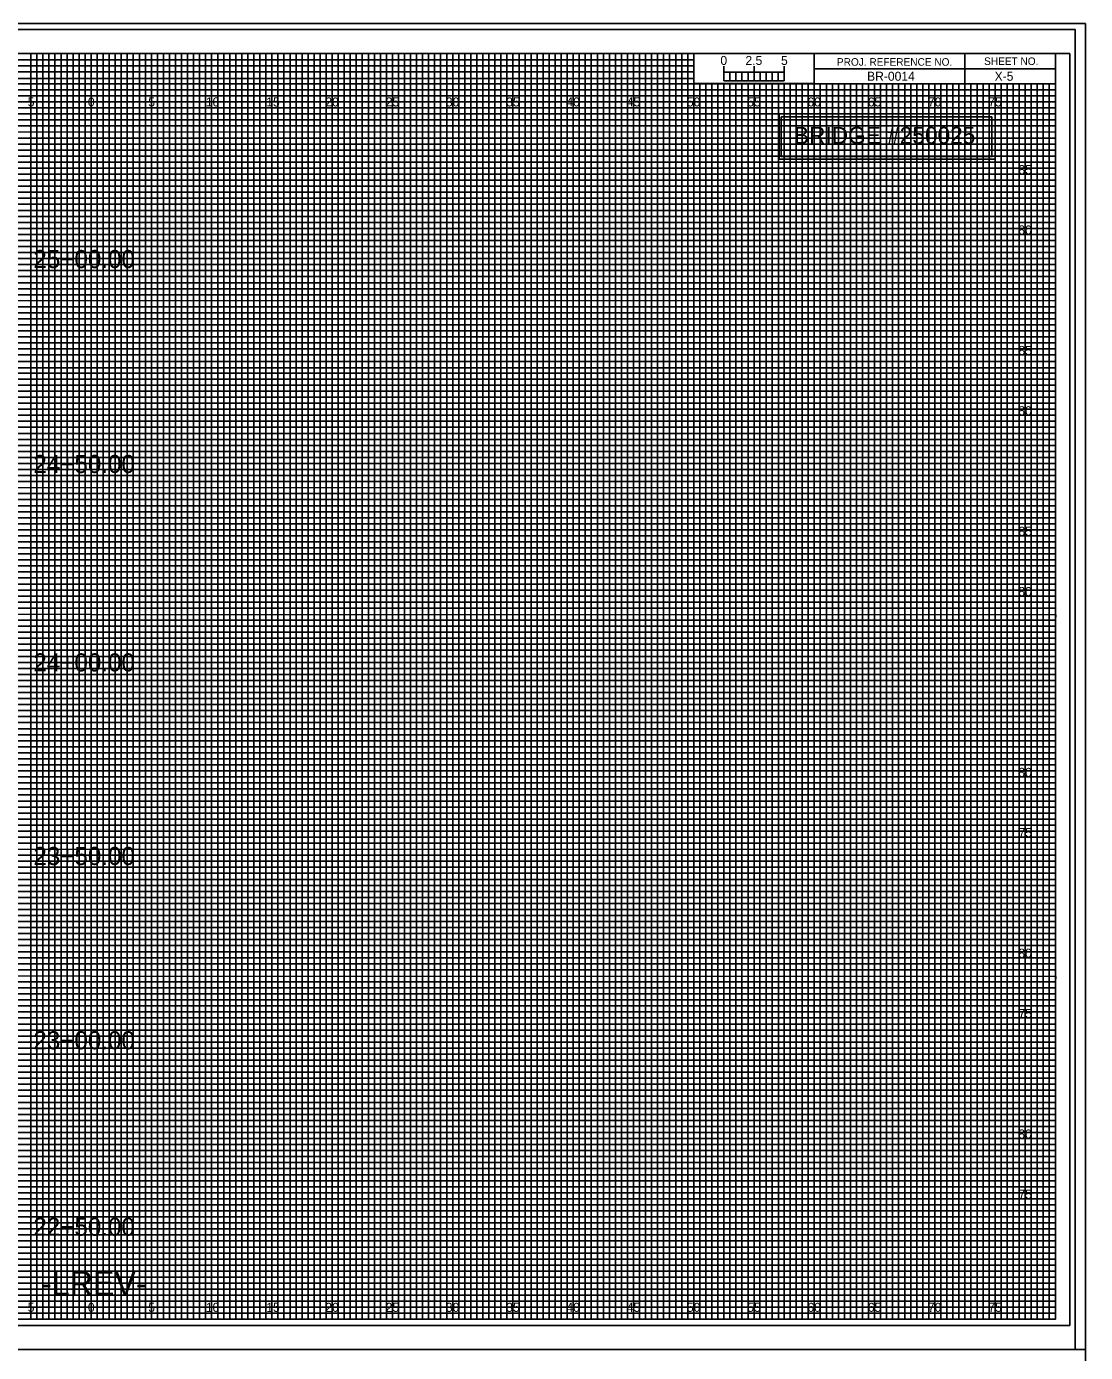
# Model space of a CAD drawing. Extents: x -8 to 533, y -20 to 768.
# Drawn here: x 74.6 to 162.5, y 437.2 to 547.2 of the extents above; entities that cross this region are included whole.
import ezdxf

# ---------------------------------------------------------------- set-up
doc = ezdxf.new("R2010")
doc.units = 0
for name, color, linetype in [('Old_Level_1', 7, 'Continuous'), ('Old_Level_34', 7, 'Continuous'), ('Prop Grid Mask', 7, 'Continuous'), ('Prop XS Alignment Label', 7, 'Continuous'), ('Prop XS Bar Scale Labels', 7, 'Continuous'), ('Prop XS Elevation Labels', 7, 'Continuous'), ('Prop XS Offset Labels', 7, 'Continuous'), ('Prop XS Project Number', 7, 'Continuous'), ('Prop XS Sheet Number', 7, 'Continuous'), ('Prop XS Station Labels', 7, 'Continuous'), ('Sheet Cross Section CELL', 7, 'Continuous'), ('Sheet Cross Section Grid Major CELL', 7, 'Continuous'), ('Sheet Cross Section Grid Middle CELL', 7, 'Continuous'), ('Sheet Cross Section Grid Minor 1 CELL', 7, 'Continuous'), ('Sheet Cross Section Grid Minor 2 CELL', 7, 'Continuous'), ('Sheet Cross Section Scale CELL', 7, 'Continuous'), ('Sheet Cutting Line CELL', 7, 'Continuous'), ('Sheet DOT Grid CELL', 7, 'Continuous'), ('Sheet Plot Border Inside CELL', 7, 'Continuous'), ('Sheet Plot Border Outside CELL', 7, 'Continuous'), ('WEI Plot Border', 7, 'Continuous')]:
    doc.layers.add(name, color=color, linetype=linetype)

msp = doc.modelspace()

# ---------------------------------------------------------------- linework, layer by layer
at = {"layer": 'Old_Level_34'}
msp.add_lwpolyline([(137.26, 539.75), (154.74, 539.75), (154.74, 536.46), (137.26, 536.46)], close=True, dxfattribs=at)
at = {"layer": 'Prop Grid Mask'}
msp.add_lwpolyline([(137.08, 540), (155, 540), (155, 536.24), (137.08, 536.24)], close=True, dxfattribs=at)
at = {"layer": 'Sheet Cross Section CELL'}
for p, q in [((152.5, 545), (152.5, 542.5)), ((152.5, 542.5), (152.5, 545)), ((160, 543.75), (140, 543.75)), ((140, 543.75), (140, 542.5)), ((140, 542.5), (160, 542.5))]:
    msp.add_line(p, q, dxfattribs=at)
for points in [[(160, 545), (0, 545), (0, 440), (160, 440)], [(140, 545), (130, 545), (130, 542.51), (140, 542.51)], [(160, 545), (140, 545), (140, 542.5), (160, 542.5)]]:
    msp.add_lwpolyline(points, close=True, dxfattribs=at)
at = {"layer": 'Sheet Cross Section Grid Major CELL'}
for p, q in [((75, 545), (70, 545)), ((75, 440), (75, 545)), ((85, 545), (80, 545)), ((80, 545), (80, 440)), ((85, 440), (85, 545)), ((95, 545), (90, 545)), ((90, 545), (90, 440)), ((95, 440), (95, 545)), ((105, 545), (100, 545)), ((100, 545), (100, 440)), ((105, 440), (105, 545)), ((115, 545), (110, 545)), ((110, 545), (110, 440)), ((115, 440), (115, 545)), ((125, 545), (120, 545)), ((120, 545), (120, 440)), ((125, 440), (125, 545)), ((130, 545), (130, 440)), ((135, 440), (135, 542.5)), ((145, 542.5), (140, 542.5)), ((140, 542.5), (140, 440)), ((145, 440), (145, 542.5)), ((155, 542.5), (150, 542.5)), ((150, 542.5), (150, 440)), ((155, 440), (155, 542.5)), ((80, 440), (75, 440)), ((90, 440), (85, 440)), ((100, 440), (95, 440)), ((110, 440), (105, 440)), ((120, 440), (115, 440)), ((130, 440), (125, 440)), ((140, 440), (135, 440)), ((150, 440), (145, 440)), ((160, 440), (155, 440)), ((160, 440), (160, 440))]:
    msp.add_line(p, q, dxfattribs=at)
for points in [[(0, 540), (160, 540), (160, 535), (0, 535)], [(0, 530), (160, 530), (160, 525), (0, 525)], [(0, 520), (160, 520), (160, 515), (0, 515)], [(0, 510), (160, 510), (160, 505), (0, 505)], [(0, 500), (160, 500), (160, 495), (0, 495)], [(0, 490), (160, 490), (160, 485), (0, 485)], [(0, 480), (160, 480), (160, 475), (0, 475)], [(0, 470), (160, 470), (160, 465), (0, 465)], [(0, 460), (160, 460), (160, 455), (0, 455)], [(0, 450), (160, 450), (160, 445), (0, 445)]]:
    msp.add_lwpolyline(points, dxfattribs=at)
at = {"layer": 'Sheet Cross Section Grid Middle CELL'}
for points in [[(72.5, 440), (77.5, 440), (77.5, 545), (82.5, 545), (82.5, 440), (87.5, 440), (87.5, 545), (92.5, 545), (92.5, 440), (97.5, 440), (97.5, 545), (102.5, 545), (102.5, 440), (107.5, 440), (107.5, 545), (112.5, 545), (112.5, 440), (117.5, 440), (117.5, 545), (122.5, 545), (122.5, 440), (127.5, 440), (127.5, 545), (129.97, 545), (130, 545), (130, 542.5), (132.5, 542.5), (132.5, 440), (137.5, 440), (137.5, 542.5), (142.5, 542.5), (142.5, 440), (147.5, 440), (147.5, 542.5), (152.5, 542.5), (152.5, 440), (157.5, 440), (157.5, 542.5)], [(0, 542.5), (137.5, 542.5)], [(0, 532.5), (160, 532.5), (160, 537.5), (0, 537.5)], [(0, 522.5), (160, 522.5), (160, 527.5), (0, 527.5)], [(0, 512.5), (160, 512.5), (160, 517.5), (0, 517.5)], [(0, 502.5), (160, 502.5), (160, 507.5), (0, 507.5)], [(0, 492.5), (160, 492.5), (160, 497.5), (0, 497.5)], [(0, 482.5), (160, 482.5), (160, 487.5), (0, 487.5)], [(0, 472.5), (160, 472.5), (160, 477.5), (0, 477.5)], [(0, 462.5), (160, 462.5), (160, 467.5), (0, 467.5)], [(0, 452.5), (160, 452.5), (160, 457.5), (0, 457.5)], [(0, 442.5), (160, 442.5), (160, 447.5), (0, 447.5)]]:
    msp.add_lwpolyline(points, dxfattribs=at)
at = {"layer": 'Sheet Cross Section Grid Minor 1 CELL'}
for p, q in [((0, 544.5), (130, 544.5)), ((130, 543.99), (0, 543.99)), ((0, 543.5), (130, 543.5)), ((130, 544.5), (130, 543.99)), ((130, 543.5), (130, 542.95)), ((130, 542.95), (0, 542.95)), ((0, 542), (160, 542))]:
    msp.add_line(p, q, dxfattribs=at)
for points in [[(0, 541.5), (135, 541.5), (160, 541.5), (160, 541), (0, 541)], [(0, 540.5), (160, 540.5), (160, 539.5), (0, 539.5)], [(0, 539), (160, 539), (160, 538.5), (0, 538.49)], [(0, 538), (160, 538), (160, 537), (0, 537)], [(0, 536.5), (160, 536.5), (160, 536), (0, 536)], [(0, 535.5), (160, 535.5), (160, 534.5), (0, 534.5)], [(0, 534), (160, 534), (160, 533.5), (0, 533.5)], [(0, 533), (160, 533), (160, 532), (0, 532)], [(0, 531.5), (160, 531.5), (160, 531), (0, 531)], [(0, 530.5), (160, 530.5), (160, 529.5), (0, 529.5)], [(0, 529), (160, 529), (160, 528.5), (0, 528.5)], [(0, 528), (160, 528), (160, 526.98), (160, 526.5), (160, 526), (0, 526)], [(0, 527), (160, 527), (160, 526.5), (0, 526.5)], [(0, 525.5), (160, 525.5), (160, 524.5), (0, 524.51)], [(0, 524.51), (160, 524.5), (160, 524), (0, 524)], [(0, 523.5), (160, 523.5), (160, 523), (0, 523)], [(0, 522), (160, 522), (160, 521.5), (0, 521.5)], [(0, 521), (160, 521), (160, 520.5), (0, 520.5)], [(-0.04, 519.45), (160, 519.45), (160, 518.94), (-0.04, 518.94)], [(0, 518.5), (160, 518.5), (160, 518), (0, 518)], [(0, 517), (160, 517), (160, 516.5), (0, 516.5)], [(0, 516), (160, 516), (160, 515.5), (0, 515.5)], [(0, 514.5), (160, 514.5), (160, 514), (0, 514)], [(0, 513.5), (160, 513.5), (160, 513), (0, 513)], [(0, 512), (160, 512), (160, 511.5), (0, 511.5)], [(0, 511), (160, 511), (160, 510.5), (0, 510.5)], [(0, 509.5), (160, 509.5), (160, 508.99), (0, 509)], [(0, 508.5), (160, 508.5), (160, 508), (0, 508)], [(0, 507), (160, 507), (160, 506.5), (0, 506.5)], [(0, 506), (160, 506), (160, 505.5), (0, 505.5)], [(0, 504.5), (160, 504.5), (160, 504), (0, 504)], [(0, 503.5), (160, 503.5), (160, 503), (0, 503)], [(0, 502), (160, 502), (160, 501.5), (0, 501.5)], [(0, 501), (160, 501), (160, 500.5), (0, 500.5)], [(0, 499.5), (160, 499.5), (160, 499), (0, 499)], [(0, 498.5), (160.03, 498.45), (160, 498), (0, 498)], [(0, 497), (160, 497), (160, 496.5), (0, 496.5)], [(0, 496), (160, 496), (160, 495.5), (0, 495.5)], [(0, 494.5), (160, 494.5), (160, 494), (0, 494)], [(0, 493.5), (160, 493.5), (160, 493), (0, 493)], [(0, 492), (160, 492), (160, 491.5), (0, 491.5)], [(0, 491), (160, 491), (160, 490.5), (0, 490.5)], [(0, 489.5), (160, 489.5), (160, 489), (0, 489)], [(0, 488.5), (160, 488.5), (160, 488), (0, 488)], [(0, 487), (160, 487), (160, 486.5), (0, 486.5)], [(0, 486), (160, 486), (160, 485.5), (0, 485.5)], [(0, 484.5), (160, 484.5), (160, 484), (0, 484)], [(0, 483.5), (160, 483.5), (160, 483), (0, 483)], [(0, 482), (160, 482), (160, 481.5), (0, 481.5)], [(0, 481), (160, 481), (160, 480.5), (0, 480.5)], [(0, 479.5), (160, 479.5), (160, 478.99), (0, 479)], [(0, 478.5), (160, 478.5), (160, 478), (0, 478)], [(0, 477), (160, 477), (160, 476.5), (0, 476.5)], [(0, 476), (160, 476), (160, 475.5), (0, 475.5)], [(0, 474.5), (160, 474.5), (160, 474), (0, 474)], [(0, 473.5), (160, 473.5), (160, 473), (0, 473)], [(0, 472), (160, 472), (160, 471.5), (0, 471.5)], [(0, 471), (160, 471), (160, 470.5), (0, 470.5)], [(0, 469.5), (160, 469.5), (160, 469), (0, 469)], [(0, 468.5), (160.03, 468.45), (160, 468), (0, 468)], [(0, 467), (160, 467), (160, 466.5), (0, 466.5)], [(0, 466), (160, 466), (160, 465.5), (0, 465.5)], [(0, 464.5), (160, 464.5), (160, 464), (0, 464)], [(0, 463.5), (160, 463.5), (160, 463), (0, 463)], [(0, 462), (160, 462), (160, 461.5), (0, 461.5)], [(0, 461), (160, 461), (160, 460.5), (0, 460.5)], [(0, 459.5), (160, 459.5), (160, 459), (0, 459)], [(0, 458.5), (160, 458.5), (160, 458), (0, 458)], [(0, 457), (160, 457), (160, 456.5), (0, 456.5)], [(0, 456), (160, 456), (160, 455.5), (0, 455.5)], [(0, 454.5), (160, 454.5), (160, 454), (0, 454)], [(0, 453.5), (160, 453.5), (160, 453), (0, 453)], [(0, 452), (160, 452), (160, 451.5), (0, 451.5)], [(0, 451), (160, 451), (160, 450.5), (0, 450.5)], [(0, 449.5), (160, 449.5), (160, 449), (0, 449)], [(0, 448.5), (160, 448.5), (160, 448), (0, 448)], [(0, 447), (160, 447), (160, 446.5), (0, 446.5)], [(0, 446), (160, 446), (160, 445.5), (0, 445.5)], [(0, 444.5), (160, 444.5), (160, 444), (0, 444)], [(0, 443.5), (160, 443.5), (160, 443), (0, 443)], [(0, 442), (160, 442), (160, 441.5), (0, 441.5)], [(0, 441), (160, 441), (160, 440.5), (0, 440.5)]]:
    msp.add_lwpolyline(points, dxfattribs=at)
at = {"layer": 'Sheet Cross Section Grid Minor 2 CELL'}
for p, q in [((133.5, 542.5), (133, 542.5)), ((133, 542.5), (133, 440)), ((133.5, 440), (133.5, 542.5)), ((134.5, 542.5), (134, 542.5)), ((134, 542.5), (134, 440)), ((134.5, 440), (134.5, 542.5)), ((133, 440), (132.5, 440)), ((134, 440), (133.5, 440))]:
    msp.add_line(p, q, dxfattribs=at)
for points in [[(75, 440), (75.5, 440), (75.5, 545), (76, 545), (76, 440)], [(76, 440), (76.5, 440), (76.5, 545), (77, 545), (77, 440)], [(77.5, 440), (78, 440), (78, 545), (78.5, 545), (78.5, 440)], [(78.5, 440), (79, 440), (79, 545), (79.5, 545), (79.5, 440)], [(80, 440), (80.5, 440), (80.5, 545), (81, 545), (81, 440)], [(81, 440), (81.5, 440), (81.5, 545), (82, 545), (82, 440)], [(82.5, 440), (83, 440), (83, 545), (83.5, 545), (83.5, 440)], [(83.5, 440), (84, 440), (84, 545), (84.5, 545), (84.5, 440)], [(85, 440), (85.5, 440), (85.5, 545), (86, 545), (86, 440)], [(86, 440), (86.5, 440), (86.5, 545), (87, 545), (87, 440)], [(87.5, 440), (88, 440), (88, 545), (88.5, 545), (88.5, 440)], [(88.5, 440), (89, 440), (89, 545), (89.5, 545), (89.5, 440)], [(90, 440), (90.5, 440), (90.5, 545), (91, 545), (91, 440)], [(91, 440), (91.5, 440), (91.5, 545), (92, 545), (92, 440)], [(92.5, 440), (93, 440), (93, 545), (93.5, 545), (93.5, 440)], [(93.5, 440), (94, 440), (94, 545), (94.5, 545), (94.5, 440)], [(95, 440), (95.5, 440), (95.5, 545), (96, 545), (96, 440)], [(96, 440), (96.5, 440), (96.5, 545), (97, 545), (97, 440)], [(97.5, 440), (98, 440), (98, 545), (98.5, 545), (98.5, 440)], [(98.5, 440), (99, 440), (99, 545), (99.5, 545), (99.5, 440)], [(100, 440), (100.5, 440), (100.5, 545), (101, 545), (101, 440)], [(101, 440), (101.5, 440), (101.5, 545), (102, 545), (102, 440)], [(102.5, 440), (103, 440), (103, 545), (103.5, 545), (103.5, 440)], [(103.5, 440), (104, 440), (104, 545), (104.5, 545), (104.5, 440)], [(105, 440), (105.5, 440), (105.5, 545), (106, 545), (106, 440)], [(106, 440), (106.5, 440), (106.5, 545), (107, 545), (107, 440)], [(107.5, 440), (108, 440), (108, 545), (108.5, 545), (108.5, 440)], [(108.5, 440), (109, 440), (109, 545), (109.5, 545), (109.5, 440)], [(110, 440), (110.5, 440), (110.5, 545), (111, 545), (111, 440)], [(111, 440), (111.5, 440), (111.5, 545), (112, 545), (112, 440)], [(112.5, 440), (113, 440), (113, 545), (113.5, 545), (113.5, 440)], [(113.5, 440), (114, 440), (114, 545), (114.5, 545), (114.5, 440)], [(115, 440), (115.5, 440), (115.5, 545), (116, 545), (116, 440)], [(116, 440), (116.5, 440), (116.5, 545), (117, 545), (117, 440)], [(117.5, 440), (118, 440), (118, 545), (118.5, 545), (118.5, 440)], [(118.5, 440), (119, 440), (119, 545), (119.5, 545), (119.5, 440)], [(120, 440), (120.5, 440), (120.5, 545), (121, 545), (121, 440)], [(121, 440), (121.5, 440), (121.5, 545), (122, 545), (122, 440)], [(122.5, 440), (123, 440), (123, 545), (123.5, 545), (123.5, 440)], [(123.5, 440), (124, 440), (124, 545), (124.5, 545), (124.5, 440)], [(125, 440), (125.5, 440), (125.5, 545), (126, 545), (126, 440)], [(126, 440), (126.5, 440), (126.5, 545), (127, 545), (127, 440)], [(127.5, 440), (128, 440), (128, 545), (128.5, 545), (128.5, 440)], [(128.5, 440), (129, 440), (129, 545), (129.5, 545), (129.5, 440)], [(130, 440), (130.5, 440), (130.5, 542.5), (131.01, 542.5), (131.01, 440)], [(131, 440), (131.5, 440), (131.5, 542.5), (132, 542.5), (132, 440)], [(135, 440), (135.49, 440), (135.49, 542.5), (136, 542.5), (136, 440)], [(136, 440), (136.5, 440), (136.5, 542.5), (137.03, 542.5), (137.03, 440)], [(137.5, 440), (138, 440), (138, 542.5), (138.5, 542.5), (138.5, 440)], [(138.5, 440), (139, 440), (139, 542.5), (139.5, 542.5), (139.5, 440)], [(140, 440), (140.5, 440), (140.5, 542.5), (141, 542.5), (141, 440)], [(141, 440), (141.5, 440), (141.5, 542.5), (142, 542.5), (142, 440)], [(142.5, 440), (143, 440), (143, 542.5), (143.5, 542.5), (143.5, 440)], [(143.5, 440), (144, 440), (144, 542.5), (144.5, 542.5), (144.5, 440)], [(145, 440), (145.5, 440), (145.5, 542.5), (146, 542.5), (146, 440)], [(146, 440), (146.5, 440), (146.5, 542.5), (147, 542.5), (147, 440)], [(147.5, 440), (148, 440), (148, 542.5), (148.5, 542.5), (148.5, 440)], [(148.5, 440), (149, 440), (149, 542.5), (149.5, 542.5), (149.5, 440)], [(150, 440), (150.5, 440), (150.5, 542.5), (151, 542.5), (151, 440)], [(151, 440), (151.5, 440), (151.5, 542.5), (152, 542.5), (152, 440)], [(152.5, 440), (153, 440), (153, 542.5), (153.5, 542.5), (153.5, 440)], [(153.5, 440), (154, 440), (154, 542.5), (154.5, 542.5), (154.5, 440)], [(155, 440), (155.5, 440), (155.5, 542.5), (156, 542.5), (156, 440)], [(156, 440), (156.5, 440), (156.5, 542.5), (157, 542.5), (157, 440)], [(157.5, 440), (158, 440), (158, 542.5), (158.5, 542.5), (158.5, 440)], [(158.5, 440), (159, 440), (159, 542.5), (159.5, 542.5), (159.5, 440)]]:
    msp.add_lwpolyline(points, dxfattribs=at)
at = {"layer": 'Sheet Cross Section Scale CELL'}
for p, q in [((132.5, 542.75), (132.5, 543.95)), ((132.5, 543.45), (132.5, 543.95)), ((135, 542.75), (135, 543.95)), ((137.5, 542.75), (137.5, 543.95)), ((137.5, 543.45), (137.5, 543.95))]:
    msp.add_line(p, q, dxfattribs=at)
for points in [[(137.5, 543.45), (132.5, 543.45), (132.5, 542.75), (137.5, 542.75)], [(132.5, 543.45), (133, 543.45), (133, 542.75), (132.5, 542.75)], [(133.5, 543.45), (134, 543.45), (134, 542.75), (133.5, 542.75)], [(134.5, 543.45), (135, 543.45), (135, 542.75), (134.5, 542.75)], [(135.5, 543.45), (136, 543.45), (136, 542.75), (135.5, 542.75)], [(136.5, 543.45), (137, 543.45), (137, 542.75), (136.5, 542.75)]]:
    msp.add_lwpolyline(points, close=True, dxfattribs=at)
at = {"layer": 'Sheet Cutting Line CELL'}
for p, q in [((161.65, 547), (-6.7, 547)), ((-6.7, 437.5), (161.65, 437.5))]:
    msp.add_line(p, q, dxfattribs=at)
at = {"layer": 'Sheet DOT Grid CELL'}
for p, q in [((75, 440), (75, 545)), ((80, 440), (80, 545)), ((85, 440), (85, 545)), ((90, 440), (90, 545)), ((95, 440), (95, 545)), ((100, 440), (100, 545)), ((105, 440), (105, 545)), ((110, 440), (110, 545)), ((115, 440), (115, 545)), ((120, 440), (120, 545)), ((125, 440), (125, 545)), ((130, 440), (130, 542.34)), ((135, 440), (135, 542.34)), ((140, 440), (140, 542.34)), ((145, 440), (145, 542.34)), ((150, 440), (150, 542.34)), ((155, 440), (155, 542.34)), ((0, 540), (160, 540)), ((0, 535), (160, 535)), ((0, 530), (160, 530)), ((0, 525), (160, 525)), ((0, 520), (160, 520)), ((0, 515), (160, 515)), ((0, 510), (160, 510)), ((0, 505), (160, 505)), ((0, 500), (160, 500)), ((0, 495), (160, 495)), ((0, 490), (160, 490)), ((0, 485), (160, 485)), ((0, 480), (160, 480)), ((0, 475), (160, 475)), ((0, 470), (160, 470)), ((0, 465), (160, 465)), ((0, 460), (160, 460)), ((0, 455), (160, 455)), ((0, 450), (160, 450)), ((0, 445), (160, 445))]:
    msp.add_line(p, q, dxfattribs=at)
at = {"layer": 'Sheet Plot Border Inside CELL'}
msp.add_lwpolyline([(-5.4, 439.5), (161.2, 439.5), (161.2, 545), (-5.4, 545)], close=True, dxfattribs=at)
at = {"layer": 'Sheet Plot Border Outside CELL'}
msp.add_lwpolyline([(-6.7, 437.5), (161.65, 437.5), (161.65, 547), (-6.7, 547)], close=True, dxfattribs=at)
at = {"layer": 'WEI Plot Border'}
for points in [[(-7.5, 437.5), (162.5, 437.5), (162.5, 547.5), (-7.5, 547.5)], [(-7.5, 327.5), (162.5, 327.5), (162.5, 437.5), (-7.5, 437.5)]]:
    msp.add_lwpolyline(points, close=True, dxfattribs=at)

# ---------------------------------------------------------------- texts
at = {"layer": 'Old_Level_1'}
msp.add_text('BRIDGE #250025', height=1.4062, rotation=360, dxfattribs=at).set_placement((138.31, 537.52))
at = {"layer": 'Prop XS Alignment Label'}
msp.add_text('-LREV-', height=2, dxfattribs=at).set_placement((75.84, 442))
at = {"layer": 'Prop XS Bar Scale Labels'}
for s, p in [('2.5', (134.29, 544.06)), ('5', (137.24, 544.06))]:
    msp.add_text(s, height=0.75, dxfattribs=at).set_placement(p)
at = {"layer": 'Prop XS Elevation Labels'}
for s, p in [('85', (156.94, 535)), ('80', (156.93, 530)), ('85', (156.94, 520)), ('80', (156.93, 515)), ('85', (156.94, 505)), ('80', (156.93, 500)), ('80', (156.93, 485)), ('75', (156.94, 480)), ('80', (156.93, 470)), ('75', (156.94, 465)), ('80', (156.93, 455)), ('75', (156.94, 450))]:
    msp.add_text(s, height=0.75, dxfattribs=at).set_placement(p)
at = {"layer": 'Prop XS Offset Labels'}
for s, p in [('5', (74.74, 540.62)), ('0', (79.73, 540.62)), ('0', (79.73, 540.62)), ('5', (84.74, 540.62)), ('10', (89.52, 540.62)), ('15', (94.53, 540.62)), ('20', (99.43, 540.62)), ('25', (104.44, 540.62)), ('30', (109.43, 540.62)), ('35', (114.44, 540.62)), ('40', (119.43, 540.62)), ('45', (124.44, 540.62)), ('50', (129.43, 540.62)), ('55', (134.44, 540.62)), ('60', (139.43, 540.62)), ('65', (144.44, 540.62)), ('70', (149.43, 540.62)), ('75', (154.44, 540.62)), ('5', (74.74, 440.62)), ('0', (79.73, 440.62)), ('0', (79.73, 440.62)), ('5', (84.74, 440.62)), ('10', (89.52, 440.62)), ('15', (94.53, 440.62)), ('20', (99.43, 440.62)), ('25', (104.44, 440.62)), ('30', (109.43, 440.62)), ('35', (114.44, 440.62)), ('40', (119.43, 440.62)), ('45', (124.44, 440.62)), ('50', (129.43, 440.62)), ('55', (134.44, 440.62)), ('60', (139.43, 440.62)), ('65', (144.44, 440.62)), ('70', (149.43, 440.62)), ('75', (154.44, 440.62))]:
    msp.add_text(s, height=0.75, dxfattribs=at).set_placement(p)
at = {"layer": 'Prop XS Project Number'}
msp.add_text('BR-0014', height=0.75, dxfattribs=at).set_placement((144.38, 542.75))
at = {"layer": 'Prop XS Sheet Number'}
msp.add_text('X-5', height=0.75, dxfattribs=at).set_placement((154.96, 542.75))
at = {"layer": 'Prop XS Station Labels'}
for s, p in [('25+00.00', (75.21, 527.21)), ('24+50.00', (75.21, 510.21)), ('24+00.00', (75.21, 493.75)), ('23+50.00', (75.21, 477.69)), ('23+00.00', (75.21, 462.4)), ('22+50.00', (75.21, 446.93))]:
    msp.add_text(s, height=1.5, dxfattribs=at).set_placement(p)
at = {"layer": 'Sheet Cross Section CELL'}
for s, p in [('PROJ. REFERENCE NO.', (141.88, 544)), ('SHEET NO.', (154.09, 544.06))]:
    msp.add_text(s, height=0.625, dxfattribs=at).set_placement(p)
at = {"layer": 'Sheet Cross Section Scale CELL'}
msp.add_text('0', height=0.75, dxfattribs=at).set_placement((132.21, 544.06))

doc.saveas('drawing.dxf')
